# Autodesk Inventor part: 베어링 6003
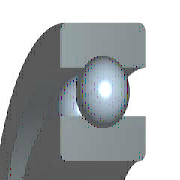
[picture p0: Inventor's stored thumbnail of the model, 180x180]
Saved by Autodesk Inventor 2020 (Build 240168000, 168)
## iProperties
Created: 2012-02
Part Number: 베어링 6003
Material: 강철, 연강
Description: 깊은 그루브 볼 베어링
Document SubType Name: Modeling
Standard: KS B 2023
Designer: mduedu
Standards Organization: KS
Language: ko-KR
Size Designation: 6003 - 17 x 35 x 10
Categories: <MemberInstance><Categories><Category DisplayName="샤프트 부품" InternalName="7f7aeb1f-a693-4053-b835-cee3144e0d98" Mnemonic="SHFT"><Category DisplayName="베어링" Inter
Density: 1 g/cm^3
Appearance: 밝은 황색
IsCustomPart: 1
Author: mduedu
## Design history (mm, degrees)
sketch "스케치" dims "d0" = 4.68 (= -0.26 x WD + 0.26 x BD)
  geometry: L1 (2.66, 13)-(7.34, 13); L2 (5, 13)-(5, 10.66); L3 (5, 13)-(5, 15.34); L4 (3.261, 11.434)-(0, 11.434); L5 (0, 8.5)-(10, 8.5); L6 (3.261, 14.566)-(0, 14.566); L7 (0, 17.5)-(10, 17.5); L8 (10, 8.5)-(10, 11.434); L9 (6.739, 11.434)-(10, 11.434); L10 (6.739, 14.566)-(10, 14.566); L11 (10, 17.5)-(10, 14.566); L12 (-1.4, 0)-(8.4, 0) reference; L13 (0, -0.3)-(0, 5.3) reference
  constraints: 22 end point, 4 point on line, 2 collinear, 2 perpendicular, 2 symmetric about line, 1 midpoint, 1 parallel, 14 other
  dimensions: "d9" = 17 diameter of L5 L12 (= WD); "d11" = 35 diameter of L7 L12 (= BD); "d12" = 10 distance between parallel lines of L8 L13 (= KB); "d13" = 22.868 diameter of L9 L12 (= 0.326 x BD + 0.674 x WD)
revolve "본체" stored, may be unused: angle "d6" = 90 deg
revolve "볼" stored, may be unused: angle "d7" = 90 deg
pattern_circular "IDS_ARRAYBALL[SIMPL:T]" dims angle "d3" = 360 deg
body "Solid1"
fillet "모깎기1" dims "d1" = 0.3 (= KRS)
other parameters: "WD" = 17 [user parameter; used in 5 equation terms], "BD" = 35 [user parameter; used in 5 equation terms], "KB" = 10 [user parameter; used in 1 equation term], "KRS" = 0.3 [user parameter; used in 1 equation term], "d4" = 0, "d5" = 0, "d8" = 0, "d14" = 0, "d15" = 0, "BBA" = 0 [user parameter], "BC0" = 3250000 [user parameter], "BC" = 6050000 [user parameter], "BR" = 17.5 (= 0.5 x BD) [user parameter], "WR" = 8.5 (= 0.5 x WD) [user parameter]
